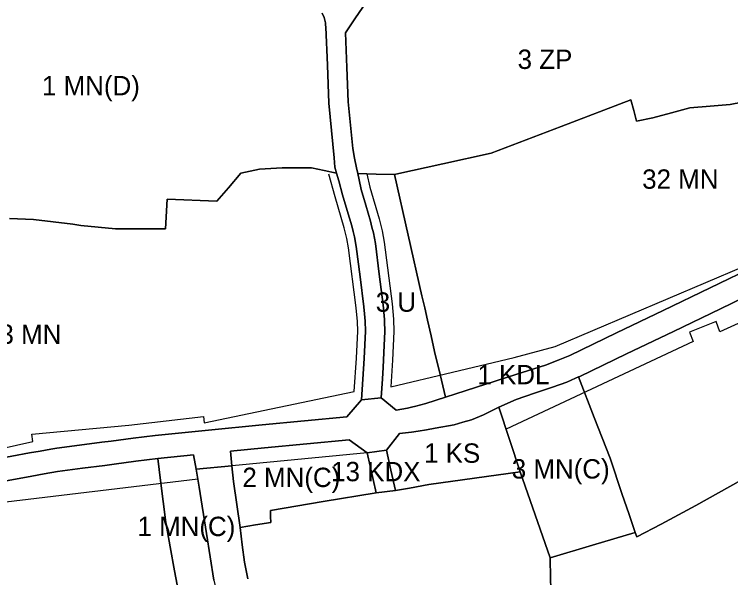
# Model space of a CAD drawing. Extents: x 7423432 to 7425824, y 5537848 to 5539677.
# Drawn here: x 7424841.5 to 7425211.1, y 5538618.6 to 5538909.6 of the extents above; entities that cross this region are included whole.
import ezdxf

# ---------------------------------------------------------------- set-up
doc = ezdxf.new("R2010")
doc.units = 0
for name, color, linetype in [('linie_rozgraniczajace', 7, 'Continuous'), ('linie_zabudowy_nieprzekraczalne', 7, 'Continuous'), ('oznaczenia_przeznaczen', 7, 'Continuous')]:
    doc.layers.add(name, color=color, linetype=linetype)

msp = doc.modelspace()

# ---------------------------------------------------------------- linework, layer by layer
at = {"layer": 'linie_rozgraniczajace'}
for points in [[(7425022.77, 5538915.5), (7425017.57, 5538907.76), (7425012.37, 5538900.02), (7425013.05, 5538882.16), (7425013.73, 5538864.3), (7425014.93, 5538852.26), (7425016.13, 5538840.23), (7425017.07, 5538835.24), (7425018, 5538830.25), (7425018.66, 5538827.33), (7425019.38, 5538824.15), (7425020.52, 5538819.12), (7425022.89, 5538810.91), (7425025.26, 5538802.69), (7425026.01, 5538799.71), (7425026.75, 5538796.74), (7425027.26, 5538793.95), (7425027.77, 5538791.16), (7425029.77, 5538775.35), (7425031.77, 5538759.53), (7425032.12, 5538755.69), (7425032.46, 5538752.01), (7425032.5, 5538751.01), (7425032.73, 5538745.83), (7425032.36, 5538738.49), (7425031.99, 5538731.15), (7425031.74, 5538727.1), (7425031.37, 5538721.28), (7425030.75, 5538711.42), (7425020.61, 5538710.39), (7425021.31, 5538721.06), (7425022.01, 5538731.72), (7425022.71, 5538745.86), (7425022.49, 5538751.17), (7425022.16, 5538754.81), (7425021.83, 5538758.45), (7425019.86, 5538774.04), (7425017.89, 5538789.63), (7425016.97, 5538794.62), (7425016.27, 5538797.44), (7425015.56, 5538800.27), (7425013.23, 5538808.32), (7425010.9, 5538816.38), (7425008.89, 5538823.52), (7425007.79, 5538827.44), (7425006.91, 5538830.57), (7425006.66, 5538833.04), (7425006.43, 5538835.41), (7425005.09, 5538849.52), (7425003.75, 5538863.64), (7425003, 5538883.29), (7425002.25, 5538902.94), (7425002.12, 5538904.05), (7425001.99, 5538905.15), (7425001.63, 5538906.53), (7425001.27, 5538907.91), (7425000.25, 5538910.22)], [(7425229.46, 5538866.56), (7425210.81, 5538862.9), (7425200.44, 5538862.11), (7425190.07, 5538861.32), (7425180.48, 5538858.75), (7425170.88, 5538856.18), (7425162.58, 5538854.35), (7425161.1, 5538859.88), (7425159.62, 5538865.4), (7425123.55, 5538851.59), (7425087.48, 5538837.77), (7425062.57, 5538832.27), (7425038.35, 5538826.93), (7425037.67, 5538826.77), (7425028.16, 5538827.05), (7425018.66, 5538827.33), (7425018, 5538830.25), (7425017.07, 5538835.24), (7425016.13, 5538840.23), (7425014.93, 5538852.26), (7425013.73, 5538864.3), (7425013.05, 5538882.16), (7425012.37, 5538900.02), (7425017.57, 5538907.76), (7425022.77, 5538915.5)], [(7425000.25, 5538910.22), (7425001.27, 5538907.91), (7425001.63, 5538906.53), (7425001.99, 5538905.15), (7425002.12, 5538904.05), (7425002.25, 5538902.94), (7425003, 5538883.29), (7425003.75, 5538863.64), (7425005.09, 5538849.52), (7425006.43, 5538835.41), (7425006.66, 5538833.04), (7425006.91, 5538830.57), (7425007.79, 5538827.44), (7425001.35, 5538828.87), (7424994.9, 5538830.3), (7424987.25, 5538830.31), (7424979.6, 5538830.32), (7424973.8, 5538829.96), (7424967.99, 5538829.59), (7424963.21, 5538828.57), (7424958.44, 5538827.55), (7424951.93, 5538820), (7424945.94, 5538813.03), (7424920.27, 5538814.07), (7424919.51, 5538798.74), (7424909.02, 5538798.76), (7424898.53, 5538798.77), (7424893.67, 5538798.78), (7424884.74, 5538799.67), (7424875.81, 5538800.57), (7424871.64, 5538801.11), (7424861.49, 5538802.36), (7424851.33, 5538803.62), (7424838.93, 5538804.14)], [(7425224.76, 5538779.96), (7425200.54, 5538768.29), (7425176.32, 5538756.61), (7425152.2, 5538744.99), (7425128.08, 5538733.36), (7425122.09, 5538730.88), (7425115.5, 5538728.42), (7425100.16, 5538723.49), (7425084.82, 5538718.56), (7425069.21, 5538713.54), (7425063.91, 5538711.84), (7425061.13, 5538723.61), (7425058.35, 5538735.37), (7425056.52, 5538743.47), (7425054.68, 5538751.57), (7425053.26, 5538757.9), (7425051.83, 5538764.22), (7425044.75, 5538795.5), (7425037.67, 5538826.77), (7425038.35, 5538826.93), (7425062.57, 5538832.27), (7425087.48, 5538837.77), (7425123.55, 5538851.59), (7425159.62, 5538865.4), (7425161.1, 5538859.88), (7425162.58, 5538854.35), (7425170.88, 5538856.18), (7425180.48, 5538858.75), (7425190.07, 5538861.32), (7425200.44, 5538862.11), (7425210.81, 5538862.9), (7425229.46, 5538866.56)], [(7424838.93, 5538804.14), (7424851.33, 5538803.62), (7424861.49, 5538802.36), (7424871.64, 5538801.11), (7424875.81, 5538800.57), (7424884.74, 5538799.67), (7424893.67, 5538798.78), (7424898.53, 5538798.77), (7424909.02, 5538798.76), (7424919.51, 5538798.74), (7424920.27, 5538814.07), (7424945.94, 5538813.03), (7424951.93, 5538820), (7424958.44, 5538827.55), (7424963.21, 5538828.57), (7424967.99, 5538829.59), (7424973.8, 5538829.96), (7424979.6, 5538830.32), (7424987.25, 5538830.31), (7424994.9, 5538830.3), (7425001.35, 5538828.87), (7425007.79, 5538827.44), (7425008.89, 5538823.52), (7425010.9, 5538816.38), (7425013.23, 5538808.32), (7425015.56, 5538800.27), (7425016.27, 5538797.44), (7425016.97, 5538794.62), (7425017.89, 5538789.63), (7425019.86, 5538774.04), (7425021.83, 5538758.45), (7425022.16, 5538754.81), (7425022.49, 5538751.17), (7425022.71, 5538745.86), (7425022.01, 5538731.72), (7425021.31, 5538721.06), (7425020.61, 5538710.39), (7425012.99, 5538701.68), (7424991.16, 5538699.62), (7424969.34, 5538697.55), (7424941.76, 5538694.83), (7424914.19, 5538692.11), (7424902.81, 5538690.61), (7424891.43, 5538689.11), (7424886.64, 5538688.51), (7424875.05, 5538687.01), (7424863.46, 5538685.51), (7424860.41, 5538684.99), (7424854.84, 5538684.03), (7424849.26, 5538683.07), (7424830.9, 5538679.6)], [(7424830.9, 5538679.6), (7424849.26, 5538683.07), (7424854.84, 5538684.03), (7424860.41, 5538684.99), (7424863.46, 5538685.51), (7424875.05, 5538687.01), (7424886.64, 5538688.51), (7424891.43, 5538689.11), (7424902.81, 5538690.61), (7424914.19, 5538692.11), (7424941.76, 5538694.83), (7424969.34, 5538697.55), (7424991.16, 5538699.62), (7425012.99, 5538701.68), (7425020.61, 5538710.39), (7425030.75, 5538711.42), (7425038.54, 5538705.13), (7425044.3, 5538706.19), (7425046.45, 5538706.73), (7425048.59, 5538707.26), (7425051.17, 5538707.92), (7425053.75, 5538708.57), (7425063.91, 5538711.84), (7425069.21, 5538713.54), (7425084.82, 5538718.56), (7425100.16, 5538723.49), (7425115.5, 5538728.42), (7425122.09, 5538730.88), (7425128.08, 5538733.36), (7425152.2, 5538744.99), (7425176.32, 5538756.61), (7425200.54, 5538768.29), (7425224.76, 5538779.96)], [(7425229.98, 5538769.16), (7425205.76, 5538757.48), (7425181.53, 5538745.81), (7425157.37, 5538734.16), (7425133.22, 5538722.52), (7425132.62, 5538722.25), (7425131.08, 5538721.57), (7425126.5, 5538719.54), (7425119.2, 5538717.01), (7425109.83, 5538713.86), (7425100.45, 5538710.71), (7425091.45, 5538706.65), (7425090.46, 5538706.19), (7425083.58, 5538702.73), (7425077.32, 5538700.11), (7425072.91, 5538698.84), (7425068.5, 5538697.57), (7425058.64, 5538695.74)], [(7425132.62, 5538722.25), (7425133.22, 5538722.52), (7425157.37, 5538734.16), (7425181.53, 5538745.81), (7425205.76, 5538757.48), (7425229.98, 5538769.16)], [(7425162.63, 5538639.66), (7425161.81, 5538641.9), (7425158.48, 5538651.7), (7425155.15, 5538661.49), (7425148.86, 5538680.28), (7425140.74, 5538701.27), (7425132.62, 5538722.25)], [(7425058.64, 5538695.74), (7425054.23, 5538694.99), (7425049.83, 5538694.24), (7425046.47, 5538693.81), (7425040.27, 5538693.04), (7425033.44, 5538684.43), (7425023.48, 5538683.11), (7425014.18, 5538689.74), (7424992.34, 5538687.67), (7424970.49, 5538685.6), (7424961.72, 5538684.74), (7424952.95, 5538683.87), (7424953.71, 5538676.36), (7424935.26, 5538674.57), (7424933.88, 5538681.99), (7424915.56, 5538680.19), (7424904.26, 5538678.7), (7424892.96, 5538677.21), (7424888.16, 5538676.6), (7424876.7, 5538675.12), (7424863.85, 5538673.4), (7424856.87, 5538672.2), (7424850.58, 5538671.12), (7424832.54, 5538667.7)], [(7424832.54, 5538667.7), (7424850.58, 5538671.12), (7424856.87, 5538672.2), (7424863.85, 5538673.4), (7424876.7, 5538675.12), (7424888.16, 5538676.6), (7424892.96, 5538677.21), (7424904.26, 5538678.7), (7424915.56, 5538680.19), (7424916.91, 5538668.79), (7424918.31, 5538657.93), (7424919.7, 5538647.06), (7424921.89, 5538634.62), (7424924.09, 5538622.18), (7424925.52, 5538614.86)], [(7424944.46, 5538617.37), (7424940.68, 5538641.41), (7424936.91, 5538665.44), (7424935.82, 5538671.58), (7424935.26, 5538674.57), (7424953.71, 5538676.36), (7424954.52, 5538668.3), (7424956.23, 5538656.45), (7424957.94, 5538644.61), (7424959.1, 5538635.61), (7424960.26, 5538626.6), (7424961.98, 5538617.94)], [(7424961.98, 5538617.94), (7424960.26, 5538626.6), (7424959.1, 5538635.61), (7424957.94, 5538644.61), (7424965.9, 5538645.89), (7424973.86, 5538647.18), (7424973.75, 5538650.28), (7424973.64, 5538653.38), (7425000.92, 5538657.9), (7425028.2, 5538662.42), (7425038.17, 5538663.69), (7425045.34, 5538664.79), (7425055.44, 5538666.73), (7425078.97, 5538669.98), (7425102.5, 5538673.23), (7425110.21, 5538651.05), (7425117.93, 5538628.87), (7425117.96, 5538627.54), (7425118.36, 5538611.67)], [(7425118.36, 5538611.67), (7425117.96, 5538627.54), (7425117.93, 5538628.87), (7425139.87, 5538635.38), (7425161.81, 5538641.9), (7425162.63, 5538639.66), (7425175.18, 5538646.25), (7425193.08, 5538655.81), (7425204.79, 5538662.43), (7425216.49, 5538669.05)], [(7425216.49, 5538669.05), (7425204.79, 5538662.43), (7425193.08, 5538655.81), (7425175.18, 5538646.25), (7425162.63, 5538639.66)]]:
    msp.add_lwpolyline(points, dxfattribs=at)
for points in [[(7425018.66, 5538827.33), (7425028.16, 5538827.05), (7425037.67, 5538826.77), (7425044.75, 5538795.5), (7425051.83, 5538764.22), (7425053.26, 5538757.9), (7425054.68, 5538751.57), (7425056.52, 5538743.47), (7425058.35, 5538735.37), (7425061.13, 5538723.61), (7425063.91, 5538711.84), (7425053.75, 5538708.57), (7425051.17, 5538707.92), (7425048.59, 5538707.26), (7425046.45, 5538706.73), (7425044.3, 5538706.19), (7425038.54, 5538705.13), (7425030.75, 5538711.42), (7425031.37, 5538721.28), (7425031.74, 5538727.1), (7425031.99, 5538731.15), (7425032.36, 5538738.49), (7425032.73, 5538745.83), (7425032.5, 5538751.01), (7425032.46, 5538752.01), (7425032.12, 5538755.69), (7425031.77, 5538759.53), (7425029.77, 5538775.35), (7425027.77, 5538791.16), (7425027.26, 5538793.95), (7425026.75, 5538796.74), (7425026.01, 5538799.71), (7425025.26, 5538802.69), (7425022.89, 5538810.91), (7425020.52, 5538819.12), (7425019.38, 5538824.15)], [(7425091.45, 5538706.65), (7425100.45, 5538710.71), (7425109.83, 5538713.86), (7425119.2, 5538717.01), (7425126.5, 5538719.54), (7425131.08, 5538721.57), (7425132.62, 5538722.25), (7425140.74, 5538701.27), (7425148.86, 5538680.28), (7425155.15, 5538661.49), (7425158.48, 5538651.7), (7425161.81, 5538641.9), (7425139.87, 5538635.38), (7425117.93, 5538628.87), (7425110.21, 5538651.05), (7425102.5, 5538673.23), (7425096.97, 5538689.94)], [(7425033.44, 5538684.43), (7425040.27, 5538693.04), (7425046.47, 5538693.81), (7425049.83, 5538694.24), (7425054.23, 5538694.99), (7425058.64, 5538695.74), (7425068.5, 5538697.57), (7425072.91, 5538698.84), (7425077.32, 5538700.11), (7425083.58, 5538702.73), (7425090.46, 5538706.19), (7425091.45, 5538706.65), (7425096.97, 5538689.94), (7425102.5, 5538673.23), (7425078.97, 5538669.98), (7425055.44, 5538666.73), (7425045.34, 5538664.79), (7425038.17, 5538663.69), (7425035.8, 5538674.06)], [(7424952.95, 5538683.87), (7424961.72, 5538684.74), (7424970.49, 5538685.6), (7424992.34, 5538687.67), (7425014.18, 5538689.74), (7425023.48, 5538683.11), (7425028.2, 5538662.42), (7425000.92, 5538657.9), (7424973.64, 5538653.38), (7424973.75, 5538650.28), (7424973.86, 5538647.18), (7424965.9, 5538645.89), (7424957.94, 5538644.61), (7424956.23, 5538656.45), (7424954.52, 5538668.3), (7424953.71, 5538676.36)], [(7425023.48, 5538683.11), (7425033.44, 5538684.43), (7425035.8, 5538674.06), (7425038.17, 5538663.69), (7425028.2, 5538662.42)], [(7424915.56, 5538680.19), (7424933.88, 5538681.99), (7424935.26, 5538674.57), (7424935.82, 5538671.58), (7424936.91, 5538665.44), (7424940.68, 5538641.41), (7424944.46, 5538617.37), (7424945.88, 5538611.34), (7424926.95, 5538607.53), (7424925.52, 5538614.86), (7424924.09, 5538622.18), (7424921.89, 5538634.62), (7424919.7, 5538647.06), (7424918.31, 5538657.93), (7424916.91, 5538668.79)]]:
    msp.add_lwpolyline(points, close=True, dxfattribs=at)
at = {"layer": 'linie_zabudowy_nieprzekraczalne'}
for points in [[(7424811.89, 5538680.1), (7424851.02, 5538688.99), (7424850.55, 5538692.7), (7424900.55, 5538697.31), (7424939.05, 5538701.77), (7424939.39, 5538698.61), (7425016.89, 5538714.83), (7425016.89, 5538714.83), (7425016.89, 5538714.83), (7425018.01, 5538731.95), (7425018.71, 5538745.88), (7425018.49, 5538750.91), (7425017.85, 5538758.02), (7425013.93, 5538789.02), (7425013.06, 5538793.78), (7425011.7, 5538799.23), (7425007.05, 5538815.28), (7425003.74, 5538827.06)], [(7425023.43, 5538827.19), (7425025, 5538820.28), (7425029.73, 5538803.89), (7425031.27, 5538797.72), (7425032.35, 5538791.87), (7425036.37, 5538760.03), (7425037.09, 5538752.15), (7425037.36, 5538745.81), (7425036.61, 5538730.89), (7425035.75, 5538717.21), (7425099.35, 5538732.38)], [(7425099.35, 5538732.38), (7425120.62, 5538737.92), (7425217.71, 5538779.25)], [(7425246.74, 5538764.34), (7425205.52, 5538745.6), (7425203.52, 5538750.99), (7425189.77, 5538745.41), (7425191.8, 5538740.54), (7425095.22, 5538695.24)], [(7425023.48, 5538683.11), (7424953.81, 5538676.37)], [(7424936.2, 5538669.42), (7424828.41, 5538656.64), (7424796.75, 5538653.06), (7424768.63, 5538649.81), (7424718.73, 5538652.01), (7424662.89, 5538660.81), (7424659.88, 5538645.33), (7424655.62, 5538624.25), (7424655.62, 5538624.25), (7424650.44, 5538592.49)]]:
    msp.add_lwpolyline(points, dxfattribs=at)

# ---------------------------------------------------------------- texts
at = {"layer": 'oznaczenia_przeznaczen'}
for s, p in [('3 ZP', (7425101.16, 5538881.34)), ('1 MN(D)', (7424855.77, 5538867.71)), ('32 MN', (7425165.43, 5538819.46)), ('3 U', (7425027.98, 5538755.94)), ('33 MN', (7424826.37, 5538739.34)), ('1 KDL', (7425080.42, 5538718.49)), ('1 KS', (7425052.88, 5538677.95)), ('3 MN(C)', (7425098.15, 5538669.8)), ('13 KDX', (7425004.96, 5538668.41)), ('2 MN(C)', (7424959.17, 5538665.41)), ('1 MN(C)', (7424905.02, 5538640.09))]:
    msp.add_text(s, height=10, dxfattribs=at).set_placement(p)

doc.saveas('drawing.dxf')
